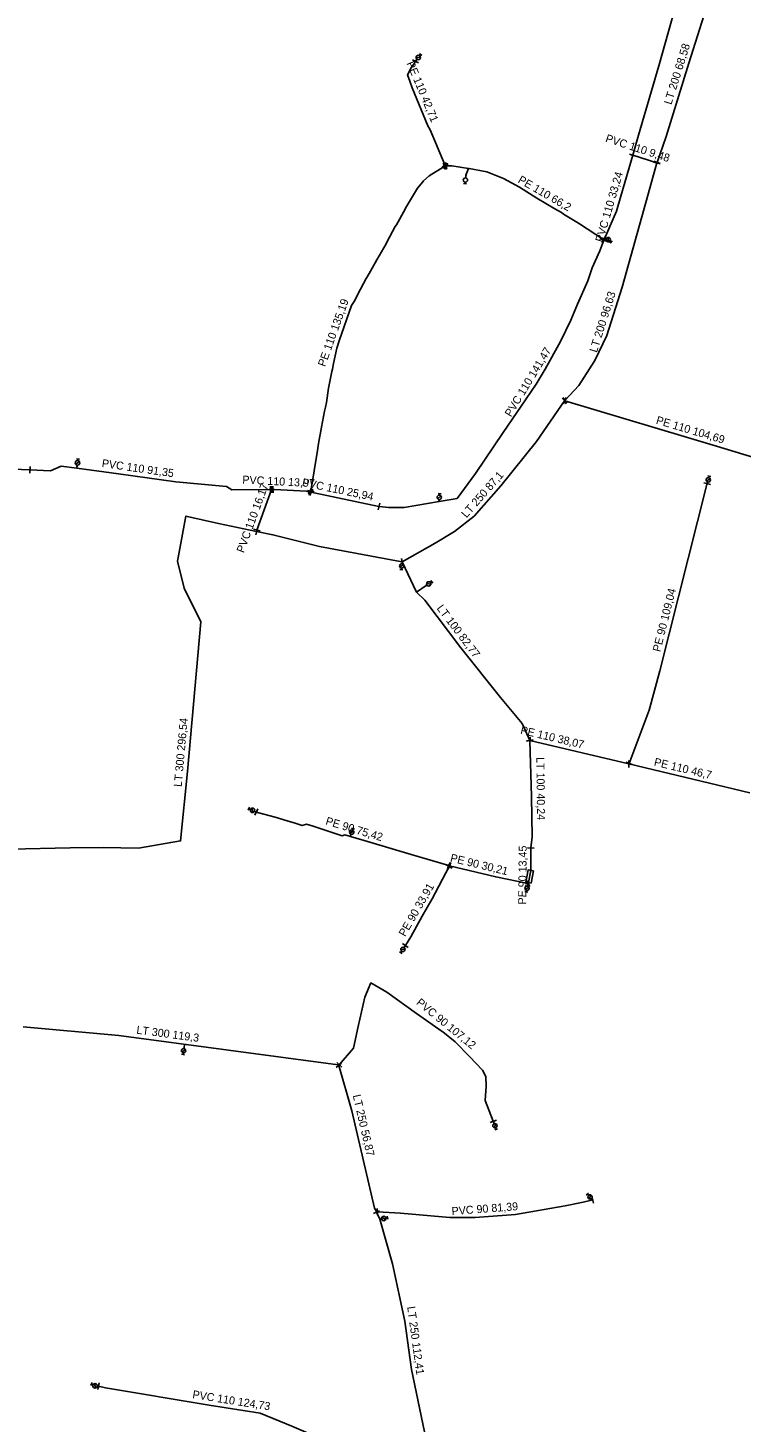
# Model space of a CAD drawing. Extents: x -736619 to -735426, y -1033122 to -1031044.
# Drawn here: x -736085 to -735818, y -1032292 to -1031769 of the extents above; entities that cross this region are included whole.
import ezdxf

# ---------------------------------------------------------------- set-up
doc = ezdxf.new("R2010")
doc.units = 0
for name, color, linetype in [('Vrstva 1', 7, 'Continuous'), ('Vrstva 17', 7, 'Continuous'), ('Vrstva 25', 7, 'Continuous'), ('Vrstva 27', 7, 'Continuous'), ('Vrstva 29', 7, 'Continuous'), ('Vrstva 63', 7, 'Continuous')]:
    doc.layers.add(name, color=color, linetype=linetype)

# ---------------------------------------------------------------- blocks, each defined once
blk = doc.blocks.new('100')
at = {"layer": 'Vrstva 1'}
blk.add_circle((0, 0), 0.127, dxfattribs=at)
blk = doc.blocks.new('133')
at = {"layer": 'Vrstva 1'}
for p, q in [((0.28, 0), (0, 0)), ((0.54, 0.58), (1.7, -0.58)), ((1.94, 0), (2.52, 0)), ((2.52, 0.58), (2.52, -0.58))]:
    blk.add_line(p, q, dxfattribs=at)
blk.add_circle((1.105, 0.003), 0.825, dxfattribs=at)
blk = doc.blocks.new('132')
at = {"layer": 'Vrstva 1'}
for p, q in [((0.3, 0), (0, 0)), ((1.96, 0), (2.52, 0)), ((2.52, 0.58), (2.52, -0.58))]:
    blk.add_line(p, q, dxfattribs=at)
blk.add_circle((1.13, -0.006), 0.825, dxfattribs=at)
blk = doc.blocks.new('147')
at = {"layer": 'Vrstva 1'}
blk.add_line((0, 1.27), (0, -1.27), dxfattribs=at)

msp = doc.modelspace()

# ---------------------------------------------------------------- linework, layer by layer
at = {"layer": 'Vrstva 17'}
for p, q in [((-735858.6, -1031816.7), (-735849.58, -1031819.63)), ((-735928.789, -1031820.76), (-735929.079, -1031820.869)), ((-735928.789, -1031820.76), (-735928.92, -1031820.539)), ((-735928.59, -1031820.649), (-735928.789, -1031820.76)), ((-735849.58, -1031819.63), (-735849.501, -1031819.388)), ((-735869.347, -1031848.47), (-735869.569, -1031848.369)), ((-735869.347, -1031848.47), (-735869.399, -1031848.579)), ((-735869.232, -1031848.139), (-735869.347, -1031848.47)), ((-735884.144, -1031908.757), (-735884.102, -1031908.713)), ((-735884.144, -1031908.757), (-735884.095, -1031908.771)), ((-735994, -1031942.05), (-735999.55, -1031957.234)), ((-735994.451, -1031942.053), (-735994, -1031942.05)), ((-735994, -1031942.05), (-735993.495, -1031942.035)), ((-735979.371, -1031942.999), (-735979.579, -1031942.96)), ((-735979.289, -1031942.689), (-735979.371, -1031942.999)), ((-735979.14, -1031943.069), (-735979.371, -1031942.999)), ((-735999.55, -1031957.234), (-735999.635, -1031957.835)), ((-735897.129, -1032036.129), (-735897.21, -1032036.14)), ((-735897.207, -1032036.237), (-735897.21, -1032036.14)), ((-735897.129, -1032036.129), (-735860.093, -1032044.951)), ((-735860.002, -1032044.735), (-735860.093, -1032044.951)), ((-735860.093, -1032044.951), (-735814.679, -1032055.817)), ((-735927.28, -1032083.12), (-735927.53, -1032083.04)), ((-735927.28, -1032083.12), (-735927.45, -1032083.38)), ((-735968.782, -1032157.944), (-735968.626, -1032157.76)), ((-735954.66, -1032212.952), (-735954.34, -1032212.9))]:
    msp.add_line(p, q, dxfattribs=at)
for points in [[(-735820.94, -1031687.85), (-735827.16, -1031708.74), (-735832.68, -1031728.09), (-735837.53, -1031745), (-735840.705, -1031754.245), (-735848.84, -1031783.16), (-735856.4, -1031809.17), (-735858.6, -1031816.7)], [(-735828.709, -1031754.04), (-735837.542, -1031782.255), (-735846.108, -1031809.675), (-735849.501, -1031819.388)], [(-735928.92, -1031820.539), (-735934.609, -1031807.21), (-735935.409, -1031805.699), (-735941.329, -1031791.5), (-735942.22, -1031788.909), (-735943.05, -1031786.569), (-735941.659, -1031783.949), (-735940.439, -1031782.199), (-735940.074, -1031781.483)], [(-735858.6, -1031816.7), (-735863.08, -1031832.031), (-735864.741, -1031837.717), (-735868.812, -1031847.137), (-735868.946, -1031847.456), (-735869.229, -1031848.13), (-735869.232, -1031848.139)], [(-735929.079, -1031820.869), (-735934.97, -1031824.439), (-735937.09, -1031826.279), (-735937.289, -1031826.649), (-735939.289, -1031829.02), (-735943.77, -1031836.6), (-735943.92, -1031836.909), (-735947.229, -1031842.85), (-735947.659, -1031843.5), (-735950.76, -1031849.279), (-735951.09, -1031849.88), (-735954.539, -1031855.89), (-735956.89, -1031860.239), (-735958.25, -1031862.51), (-735958.529, -1031862.97), (-735961.71, -1031868.76), (-735962.859, -1031871.13), (-735964.01, -1031873.065), (-735968.72, -1031886.279), (-735969.539, -1031889.069), (-735970.869, -1031894.84), (-735971.239, -1031896.89), (-735971.407, -1031897.756), (-735972.64, -1031904.09), (-735973.479, -1031909.439), (-735973.859, -1031911.14), (-735974.159, -1031912.63), (-735975.31, -1031918.67), (-735976.42, -1031924.819), (-735976.75, -1031927.479), (-735979.289, -1031942.689)], [(-735869.569, -1031848.369), (-735878.539, -1031842.43), (-735879.539, -1031841.76), (-735884.56, -1031838.779), (-735885.26, -1031838.18), (-735887.779, -1031836.789), (-735894.609, -1031832.829), (-735901.02, -1031828.75), (-735907.05, -1031825.399), (-735913.319, -1031822.939), (-735919.92, -1031821.739), (-735920.17, -1031821.64), (-735926.38, -1031820.67), (-735928.59, -1031820.649)], [(-735884.102, -1031908.713), (-735878.759, -1031903.099), (-735872.802, -1031893.663), (-735868.297, -1031884.257), (-735862.588, -1031866.235), (-735852.859, -1031831.287), (-735849.58, -1031819.63)], [(-735869.399, -1031848.579), (-735871, -1031852.515), (-735873.8, -1031858.891), (-735875.401, -1031863.806), (-735879.36, -1031872.581), (-735881.842, -1031878.541), (-735885.65, -1031886.582), (-735891.404, -1031896.963), (-735894.777, -1031902.525), (-735900.446, -1031910.825), (-735907.157, -1031920.639), (-735917.613, -1031936.024), (-735924.438, -1031945.367), (-735931.222, -1031946.602), (-735944.272, -1031948.739), (-735950.243, -1031948.793), (-735953.571, -1031948.409), (-735953.75, -1031948.388)], [(-735884.144, -1031908.757), (-735894.711, -1031923.994), (-735908.086, -1031940.709), (-735918.081, -1031952.053), (-735925.443, -1031957.814), (-735932.72, -1031962.201), (-735945.056, -1031969.214)], [(-735884.095, -1031908.771), (-735827.148, -1031925.838), (-735783.882, -1031938.884)], [(-736084.632, -1031934.715), (-736097.47, -1031934.21), (-736112.73, -1031932.78), (-736129.48, -1031929.89), (-736132.066, -1031929.318), (-736133.33, -1031929.133)], [(-736084.632, -1031934.715), (-736076.89, -1031935.02), (-736072.94, -1031933.29), (-736067.081, -1031934.064), (-736051.44, -1031936.13), (-736029.94, -1031939.22), (-736010.87, -1031940.98), (-736008.88, -1031942.14), (-735994.992, -1031942.056), (-735994.451, -1031942.053)], [(-735979.579, -1031942.96), (-735981.004, -1031942.637), (-735992.99, -1031942.02), (-735993.495, -1031942.035)], [(-735953.75, -1031948.388), (-735978.078, -1031943.331), (-735979.14, -1031943.069)], [(-735830.678, -1031939.826), (-735830.773, -1031940.203), (-735848.396, -1032010.033), (-735852.477, -1032024.785), (-735860.002, -1032044.735)], [(-735999.635, -1031957.835), (-736013.872, -1031954.746), (-736026.153, -1031952.022), (-736029.306, -1031968.97), (-736026.808, -1031979.076), (-736020.567, -1031991.616), (-736025.61, -1032047.78), (-736028.164, -1032073.797), (-736043.98, -1032076.566), (-736057.128, -1032076.327), (-736069.539, -1032076.342), (-736091.953, -1032076.886), (-736106.399, -1032078.551), (-736102.005, -1032098.49), (-736096.805, -1032119.288), (-736090.451, -1032143.226)], [(-735945.056, -1031969.214), (-735945.791, -1031969.069), (-735976.072, -1031963.357), (-735993.525, -1031958.995), (-735999.635, -1031957.835)], [(-735897.21, -1032036.14), (-735897.692, -1032035.043), (-735900.075, -1032029.724), (-735908.246, -1032020.035), (-735923.04, -1032001.471), (-735936.603, -1031983.541), (-735939.737, -1031980.543), (-735945.056, -1031969.214)], [(-735896.77, -1032076.44), (-735896.33, -1032072.25), (-735896.523, -1032057.102), (-735897.207, -1032036.237)], [(-735927.53, -1032083.04), (-735941.68, -1032078.87), (-735957.19, -1032074.31), (-735964.46, -1032072.12), (-735966.59, -1032071.55), (-735967.61, -1032071.94), (-735978.06, -1032068.39), (-735978.42, -1032068.3), (-735980.94, -1032067.5), (-735982.59, -1032067.97), (-735985.16, -1032067.2), (-735988.16, -1032066.29), (-735992.65, -1032064.94), (-735999.33, -1032063.09), (-735999.71, -1032062.95)], [(-735896.77, -1032076.44), (-735896.76, -1032076.8), (-735896.84, -1032084.85), (-735897.7, -1032089.41), (-735897.82, -1032089.79)], [(-735927.45, -1032083.38), (-735933.84, -1032095.56), (-735937.55, -1032102), (-735941.77, -1032109.81), (-735943.87, -1032113.03)], [(-735897.82, -1032089.79), (-735909.98, -1032087.32), (-735927.28, -1032083.12)], [(-735910.899, -1032178.938), (-735913.9, -1032171.14), (-735913.52, -1032165.73), (-735913.65, -1032162.11), (-735914.91, -1032159.71), (-735919.793, -1032154.644), (-735925.14, -1032149.09), (-735929.75, -1032145.32), (-735930, -1032145.27), (-735939.65, -1032138.5), (-735950.79, -1032130.48), (-735956.77, -1032127.03), (-735959.12, -1032132.35), (-735961.61, -1032143.37), (-735963.29, -1032151.46), (-735968.626, -1032157.76)], [(-736087.139, -1032143.448), (-736051.26, -1032146.807), (-735969.082, -1032157.753), (-735968.782, -1032157.944)], [(-735968.782, -1032157.944), (-735963.915, -1032175.016), (-735955.483, -1032211.476), (-735954.74, -1032212.779), (-735954.66, -1032212.952)], [(-735954.34, -1032212.9), (-735945.67, -1032213.43), (-735927.2, -1032215.02), (-735917.69, -1032215.05), (-735902.6, -1032213.92), (-735883.95, -1032210.63), (-735877.22, -1032209.19), (-735873.604, -1032208.416)], [(-735954.66, -1032212.952), (-735953.407, -1032215.657), (-735948.624, -1032232.346), (-735944.072, -1032253.819), (-735941.595, -1032272.005), (-735934.779, -1032304.372), (-735938.314, -1032305.089), (-735938.478, -1032308.409), (-735942.432, -1032314.719), (-735943.354, -1032318.926)], [(-736058.928, -1032278.254), (-736056.268, -1032278.805), (-736017.452, -1032285.347), (-735998.364, -1032288.387), (-735986.426, -1032293.223), (-735959.541, -1032304.754), (-735943.596, -1032318.709)]]:
    msp.add_lwpolyline(points, dxfattribs=at)
at = {"layer": 'Vrstva 27'}
msp.add_lwpolyline([(-735898.683, -1032089.225), (-735897.823, -1032084.665), (-735895.857, -1032085.035), (-735896.717, -1032089.595), (-735898.683, -1032089.225)], dxfattribs=at)
at = {"layer": 'Vrstva 63'}
for p, q in [((-736067.081, -1031934.064), (-736066.96, -1031933.15)), ((-735830.678, -1031939.826), (-735830.579, -1031939.48)), ((-735945.056, -1031969.214), (-735945.098, -1031969.603)), ((-735939.737, -1031980.543), (-735936.015, -1031978.048)), ((-735999.437, -1032063.05), (-736000.16, -1032062.79)), ((-735943.87, -1032113.03), (-735944.18, -1032113.55)), ((-736026.664, -1032150.083), (-736026.836, -1032151.375)), ((-735910.899, -1032178.938), (-735910.66, -1032179.56)), ((-735953.407, -1032215.657), (-735953.048, -1032215.592))]:
    msp.add_line(p, q, dxfattribs=at)
for points in [[(-735940.074, -1031781.483), (-735939.96, -1031781.26), (-735939.71, -1031780.949)], [(-735920.17, -1031821.64), (-735921.149, -1031824.239), (-735921.208, -1031824.921)], [(-735868.946, -1031847.456), (-735868.853, -1031847.487), (-735868.639, -1031847.661)], [(-735931.222, -1031946.602), (-735931.251, -1031946.338), (-735931.23, -1031946.089)], [(-735964.46, -1032072.12), (-735964.43, -1032071.96), (-735964.31, -1032071.58)], [(-735897.82, -1032089.79), (-735897.92, -1032090.05), (-735898, -1032090.46)], [(-735873.604, -1032208.416), (-735873.62, -1032208.34), (-735873.86, -1032208.08)], [(-736058.928, -1032278.254), (-736058.983, -1032278.673), (-736059.234, -1032278.567)]]:
    msp.add_lwpolyline(points, dxfattribs=at)

# ---------------------------------------------------------------- block references
at = {"layer": 'Vrstva 25'}
for name, p, xscale, yscale, rotation in [('133', (-735939.71, -1031780.949), 0.9999999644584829, 0.999999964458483, 50.999998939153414), ('132', (-735921.208, -1031824.921), 1.0011216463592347, 1.0011216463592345, -96.58261022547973), ('133', (-735868.639, -1031847.661), 0.9999999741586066, 0.9999999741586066, -39.999998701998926), ('133', (-736066.96, -1031933.15), 0.9999999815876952, 0.9999999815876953, 82.0000004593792), ('133', (-735830.579, -1031939.48), 0.9999999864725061, 0.9999999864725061, 74.0000013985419), ('133', (-735931.23, -1031946.089), 0.9999999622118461, 0.999999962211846, 85.0000001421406), ('133', (-735945.098, -1031969.603), 1.000191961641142, 1.000191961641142, -97.08900113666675), ('133', (-735936.015, -1031978.048), 0.9999999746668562, 0.999999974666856, 34.00000045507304), ('133', (-736000.16, -1032062.79), 1.0296949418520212, 1.0296949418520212, 155.86621099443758), ('133', (-735964.31, -1032071.58), 0.9999999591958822, 0.9999999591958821, 72.00000054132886), ('133', (-735898, -1032090.46), 0.999999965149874, 0.9999999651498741, -102.0000000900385), ('133', (-735944.18, -1032113.55), 0.9999999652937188, 0.9999999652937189, -121.99999738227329), ('133', (-736026.836, -1032151.375), 0.9999999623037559, 0.999999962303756, -99.00000013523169), ('133', (-735910.66, -1032179.56), 0.9999999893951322, 0.9999999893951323, -70.00000094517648), ('133', (-735873.86, -1032208.08), 0.9999999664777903, 0.9999999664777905, 132.99999806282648), ('133', (-735953.048, -1032215.592), 1.0073309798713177, 1.007330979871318, 12.138907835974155), ('133', (-736059.234, -1032278.567), 1.022584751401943, 1.022584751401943, 154.18102569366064)]:
    msp.add_blockref(name, p, dxfattribs=dict(at, xscale=xscale, yscale=yscale, rotation=rotation))
at = {"layer": 'Vrstva 29'}
for p, xscale, yscale, rotation in [((-735940.074, -1031781.483), 0.999999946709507, 0.999999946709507, 62.999999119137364), ((-735858.6, -1031816.7), 0.9999999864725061, 0.9999999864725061, 74.0000013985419), ((-735928.92, -1031820.539), 0.9999999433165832, 0.999999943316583, -64.0000000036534), ((-735929.079, -1031820.869), 1.0138864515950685, 1.0138864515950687, 27.5653151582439), ((-735928.789, -1031820.76), 1.0365458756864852, 1.0365458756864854, -21.97149085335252), ((-735928.59, -1031820.649), 1.0009847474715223, 1.0009847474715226, 14.22432628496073), ((-735849.58, -1031819.63), 0.9999999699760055, 0.9999999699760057, 73.00000033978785), ((-735849.501, -1031819.388), 0.9999999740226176, 0.9999999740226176, 71.00000039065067), ((-735869.399, -1031848.579), 0.9999999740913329, 0.9999999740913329, 65.99999939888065), ((-735869.347, -1031848.47), 0.9999999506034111, 0.9999999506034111, 67.99999971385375), ((-735869.232, -1031848.139), 0.9999999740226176, 0.9999999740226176, 71.00000039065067), ((-735869.569, -1031848.369), 0.9999999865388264, 0.9999999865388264, -30.00000044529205), ((-735884.102, -1031908.713), 0.9999999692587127, 0.9999999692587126, 46.00000080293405), ((-735884.144, -1031908.757), 1.0296949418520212, 1.0296949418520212, 24.133789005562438), ((-735884.095, -1031908.771), 1.035124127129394, 1.0351241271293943, -22.503654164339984), ((-736084.632, -1031934.715), 1.0002788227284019, 1.0002788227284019, -3.2906995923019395), ((-735994, -1031942.05), 0.9999999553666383, 0.9999999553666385, 1.000000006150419), ((-735993.495, -1031942.035), 0.9999999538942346, 0.9999999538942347, 2.0000000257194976), ((-735979.289, -1031942.689), 0.999999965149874, 0.9999999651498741, 77.9999999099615), ((-735979.371, -1031942.999), 0.9999999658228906, 0.9999999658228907, -62.00000017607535), ((-735979.579, -1031942.96), 1.0028916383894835, 1.0028916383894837, -13.697207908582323), ((-735979.14, -1031943.069), 1.0365458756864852, 1.0365458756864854, -21.97149085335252), ((-735830.678, -1031939.826), 0.9999999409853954, 0.9999999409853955, 75.99999967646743), ((-735953.75, -1031948.388), 1.0073309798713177, 1.007330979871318, -12.138907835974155), ((-735999.55, -1031957.234), 0.9999999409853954, 0.9999999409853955, 75.99999967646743), ((-735999.635, -1031957.835), 1.0060666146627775, 1.0060666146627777, 167.3452647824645), ((-735945.056, -1031969.214), 1.00837761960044, 1.00837761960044, 11.626378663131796), ((-735897.207, -1032036.237), 0.9999999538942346, 0.9999999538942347, 92.0000000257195), ((-735897.21, -1032036.14), 0.999999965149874, 0.9999999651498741, -77.9999999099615), ((-735897.129, -1032036.129), 1.0002788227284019, 1.0002788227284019, 176.70930040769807), ((-735860.002, -1032044.735), 0.9999999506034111, 0.9999999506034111, 67.99999971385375), ((-735999.71, -1032062.95), 1.0296949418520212, 1.0296949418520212, 155.86621099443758), ((-735896.77, -1032076.44), 0.9999999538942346, 0.9999999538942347, 87.9999999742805), ((-735927.45, -1032083.38), 0.9999999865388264, 0.9999999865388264, 59.99999955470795), ((-735927.53, -1032083.04), 1.0335064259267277, 1.033506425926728, -23.04128150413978), ((-735927.28, -1032083.12), 1.035124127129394, 1.0351241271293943, -22.503654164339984), ((-735897.82, -1032089.79), 0.9999999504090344, 0.9999999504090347, 31.000001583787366), ((-735943.87, -1032113.03), 0.9999999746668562, 0.999999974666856, -124.00000045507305), ((-735968.782, -1032157.944), 0.9999999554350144, 0.9999999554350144, 126.99999920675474), ((-735968.626, -1032157.76), 0.9999999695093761, 0.9999999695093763, -131.00000134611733), ((-735910.899, -1032178.938), 0.999999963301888, 0.9999999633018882, 110.99999898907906), ((-735873.604, -1032208.416), 1.0045862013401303, 1.00458620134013, 13.17409066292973), ((-735954.66, -1032212.952), 0.9999999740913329, 0.9999999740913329, -65.99999939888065), ((-735954.34, -1032212.9), 1.0002788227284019, 1.0002788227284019, 3.2906995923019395), ((-736058.928, -1032278.254), 1.0045862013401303, 1.00458620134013, 166.82590933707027)]:
    msp.add_blockref('147', p, dxfattribs=dict(at, xscale=xscale, yscale=yscale, rotation=rotation))
for p in [(-735994.451, -1031942.053), (-735860.093, -1032044.951)]:
    msp.add_blockref('147', p, dxfattribs=at)
at = {"layer": 'Vrstva 63'}
for p, xscale, yscale, rotation in [((-735939.96, -1031781.26), 0.9999999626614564, 0.9999999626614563, 57.00000159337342), ((-735921.149, -1031824.239), 0.9999999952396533, 0.9999999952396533, 77.00000056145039), ((-735868.853, -1031847.487), 0.9999999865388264, 0.9999999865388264, -30.00000044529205), ((-736066.978, -1031933.287), 0.9999999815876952, 0.9999999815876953, 82.0000004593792), ((-735931.251, -1031946.338), 0.9999999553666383, 0.9999999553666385, 91.00000000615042), ((-735964.43, -1032071.96), 0.9999999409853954, 0.9999999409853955, 75.99999967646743), ((-735897.92, -1032090.05), 0.9999999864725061, 0.9999999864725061, 74.0000013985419), ((-735910.808, -1032179.176), 0.9999999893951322, 0.9999999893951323, -70.00000094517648), ((-735873.62, -1032208.34), 0.9999999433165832, 0.999999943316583, -64.0000000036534), ((-736058.983, -1032278.673), 0.9999999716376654, 0.9999999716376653, 29.999998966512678)]:
    msp.add_blockref('100', p, dxfattribs=dict(at, xscale=xscale, yscale=yscale, rotation=rotation))

# ---------------------------------------------------------------- texts
for s, rotation, p in [('LT 200 68,58', 72.65, (-735844.125, -1031797.961)), ('PE 110 42,71', 292.63, (-735943.461, -1031782.225)), ('PVC 110 9,48', 342, (-735869.062, -1031811.617)), ('PE 110 66,2', 329.9, (-735901.885, -1031826.762)), ('PVC 110 33,24', 73.71, (-735869.866, -1031849.554)), ('LT 200 96,63', 72.42, (-735872.08, -1031890.9)), ('PE 110 135,19', 70.38, (-735973.963, -1031896.221)), ('PVC 110 141,47', 58.77, (-735904.258, -1031915.075)), ('PE 110 104,69', 343.32, (-735850.085, -1031917.294)), ('PVC 110 91,35', 351.82, (-736057.834, -1031933.594)), ('PVC 110 13,97', 357.05, (-736005.038, -1031939.796)), ('PVC 110 25,94', 348.26, (-735982.8, -1031940.715)), ('LT 250 87,1', 48.62, (-735920.96, -1031952.902)), ('PVC 110 16,17', 69.92, (-736004.465, -1031966.019)), ('PE 90 109,04', 75.84, (-735848.3, -1032003.12)), ('LT 100 82,77', 307.11, (-735932.264, -1031986.625)), ('LT 300 296,54', 84.87, (-736027.742, -1032053.635)), ('PE 110 38,07', 346.6, (-735900.908, -1032033.583)), ('LT 100 40,24', 270.73, (-735894.756, -1032042.377)), ('PE 110 46,7', 346.54, (-735850.837, -1032045.519)), ('PE 90 75,42', 343.24, (-735974, -1032067.576)), ('PE 90 30,21', 346.35, (-735927.238, -1032081.482)), ('PE 90 13,45', 89.43, (-735898.567, -1032097.657)), ('PE 90 33,91', 60.05, (-735943.955, -1032109.911)), ('PVC 90 107,12', 320.72, (-735940.016, -1032134.855)), ('LT 300 119,3', 352.41, (-736044.841, -1032146.046)), ('LT 250 56,87', 283.02, (-735963.607, -1032169.242)), ('PVC 90 81,39', 4.28, (-735926.419, -1032214.098)), ('LT 250 112,41', 277.76, (-735943.184, -1032248.491)), ('PVC 110 124,73', 350.95, (-736023.848, -1032282.707))]:
    msp.add_text(s, height=2.99999, rotation=rotation, dxfattribs=at).set_placement(p)

doc.saveas('drawing.dxf')
